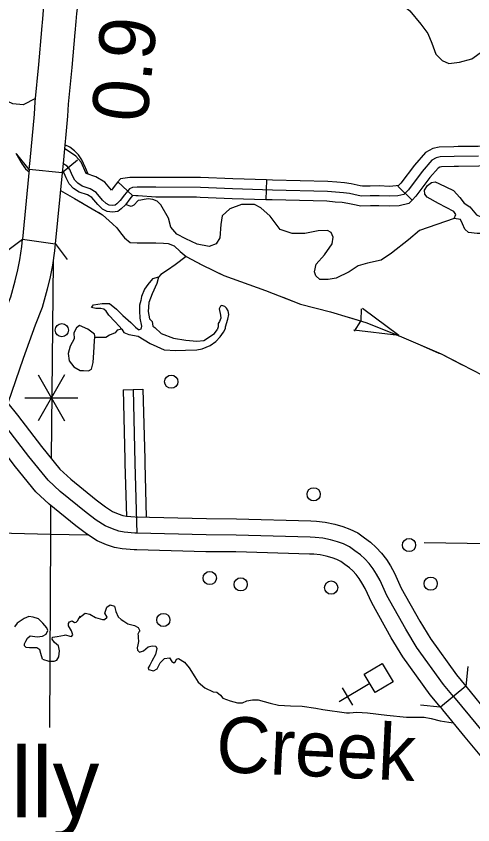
# Model space of a CAD drawing. Extents: x 1369979 to 1371646, y 379997 to 381064.
# Drawn here: x 1370730.7 to 1370771.1, y 380459 to 380530.6 of the extents above; entities that cross this region are included whole.
import ezdxf

# ---------------------------------------------------------------- set-up
doc = ezdxf.new("R2010")
doc.units = 0
doc.layers.add('R_Border Notes', color=7, linetype='Continuous')
doc.layers.add('R_Draft', color=7, linetype='Continuous')

msp = doc.modelspace()

# ---------------------------------------------------------------- linework, layer by layer
at = {"layer": 'R_Border Notes'}
for p, q in [((1370731.853, 380517.038), (1370731.853, 380517.038)), ((1370752.855, 380516.113), (1370752.803, 380514.356)), ((1370739.706, 380515.944), (1370740.998, 380514.746)), ((1370764.488, 380515.56), (1370765.732, 380514.318)), ((1370761.235, 380504.703), (1370761.199, 380503.633)), ((1370764.561, 380502.327), (1370761.337, 380504.732)), ((1370760.628, 380502.711), (1370761.195, 380503.62)), ((1370764.561, 380502.327), (1370760.567, 380502.798)), ((1370734.974, 380498.843), (1370732.63, 380494.784)), ((1370732.63, 380498.843), (1370734.974, 380494.784)), ((1370740.161, 380497.53), (1370741.918, 380497.572)), ((1370731.458, 380496.814), (1370736.146, 380496.814)), ((1370759.287, 380469.915), (1370761.993, 380471.537)), ((1370760.493, 380469.613), (1370759.589, 380471.121))]:
    msp.add_line(p, q, dxfattribs=at)
for points in [[(1370732.968, 380529.439), (1370733.061, 380530.397), (1370733.109, 380531.14), (1370733.214, 380531.981), (1370733.366, 380532.79), (1370733.562, 380533.756), (1370733.744, 380534.501), (1370733.962, 380535.343), (1370734.086, 380535.716)], [(1370736.87, 380534.806), (1370736.585, 380533.785), (1370736.421, 380533.117), (1370736.241, 380532.229), (1370736.11, 380531.53), (1370736.027, 380530.863), (1370735.981, 380530.161), (1370735.885, 380529.159)], [(1370756.709, 380532.362), (1370757.256, 380532.103), (1370757.558, 380532.031), (1370758.004, 380532.031), (1370758.436, 380532.103), (1370758.796, 380532.304), (1370759.17, 380532.722), (1370759.415, 380533.039), (1370759.818, 380533.328), (1370760.063, 380533.4), (1370760.869, 380533.385), (1370761.906, 380533.011), (1370763.403, 380532.593), (1370764.396, 380532.059), (1370765.548, 380531.094), (1370766.498, 380529.912)], [(1370766.498, 380529.912), (1370767.143, 380529.084), (1370767.489, 380528.219), (1370767.834, 380527.254), (1370768.395, 380526.706), (1370769, 380526.418), (1370769.936, 380526.534), (1370771.016, 380526.836), (1370771.966, 380527.528), (1370772.311, 380527.715), (1370772.743, 380527.787), (1370773.161, 380527.643), (1370773.852, 380527.297), (1370774.283, 380526.721), (1370774.586, 380525.842), (1370774.902, 380525.035), (1370774.974, 380524.631), (1370774.917, 380524.271), (1370775.046, 380524.041), (1370775.406, 380523.724), (1370775.838, 380523.551), (1370776.932, 380523.306)], [(1370731.853, 380517.038), (1370731.931, 380517.84), (1370732.321, 380521.954), (1370732.369, 380523.026), (1370732.701, 380526.34), (1370732.967, 380529.425)], [(1370735.886, 380529.173), (1370735.618, 380526.068), (1370735.292, 380522.815), (1370735.245, 380521.751), (1370734.848, 380517.559), (1370734.768, 380516.749)], [(1370732.399, 380523.334), (1370731.306, 380522.765), (1370730.388, 380522.853), (1370729.559, 380523.227), (1370728.257, 380524.353)], [(1370737.052, 380516.628), (1370736.836, 380517.197), (1370736.498, 380517.893), (1370736.21, 380518.333), (1370735.864, 380518.705), (1370735.45, 380519.031), (1370735.005, 380519.225)], [(1370769.829, 380519.066), (1370769.444, 380519.061), (1370768.127, 380519.033), (1370767.561, 380518.907), (1370766.927, 380518.548), (1370765.945, 380517.43), (1370764.748, 380515.82), (1370764.488, 380515.56)], [(1370775.967, 380519.371), (1370774.882, 380519.308), (1370771.589, 380519.087), (1370769.829, 380519.066)], [(1370730.649, 380518.485), (1370731.139, 380517.65), (1370731.528, 380517.102), (1370731.833, 380516.837)], [(1370731.853, 380517.038), (1370730.739, 380518.398)], [(1370736.877, 380516.688), (1370736.458, 380517.685), (1370735.968, 380518.224), (1370734.975, 380518.899)], [(1370771.624, 380518.209), (1370769.459, 380518.183), (1370768.233, 380518.156), (1370767.881, 380518.078), (1370767.489, 380517.856), (1370766.628, 380516.877), (1370765.415, 380515.244), (1370765.011, 380514.84), (1370764.463, 380514.709), (1370763.733, 380514.67), (1370762.82, 380514.709), (1370762.033, 380514.696), (1370761.268, 380514.683), (1370760.968, 380514.748), (1370760.194, 380514.905), (1370759.659, 380514.983), (1370758.238, 380515.101), (1370753.372, 380515.218), (1370749.837, 380515.323), (1370746.994, 380515.453), (1370743.068, 380515.466), (1370741.411, 380515.466), (1370740.981, 380515.453), (1370740.733, 380515.323), (1370740.563, 380515.14), (1370740.29, 380514.801), (1370739.911, 380514.304), (1370739.611, 380513.991), (1370739.468, 380513.886), (1370739.207, 380513.847), (1370738.933, 380513.886), (1370738.672, 380514.017), (1370738.346, 380514.33), (1370737.778, 380515.016)], [(1370731.178, 380517.594), (1370731.528, 380517.102), (1370731.833, 380516.837)], [(1370736.128, 380517.863), (1370734.768, 380516.749)], [(1370737.778, 380515.016), (1370737.253, 380515.322), (1370736.525, 380515.57), (1370736.147, 380515.818), (1370735.873, 380516.105), (1370735.664, 380516.549), (1370735.455, 380517.045), (1370735.194, 380517.333), (1370734.829, 380517.581)], [(1370776.069, 380517.616), (1370774.992, 380517.553), (1370771.659, 380517.33), (1370769.85, 380517.308)], [(1370731.853, 380517.038), (1370731.249, 380510.88)], [(1370734.768, 380516.749), (1370731.853, 380517.038)], [(1370735.296, 380515.954), (1370735.129, 380516.311), (1370734.954, 380516.726), (1370734.784, 380516.913)], [(1370769.85, 380517.308), (1370769.474, 380517.304), (1370768.339, 380517.28), (1370768.2, 380517.249), (1370768.052, 380517.165), (1370767.312, 380516.324), (1370766.083, 380514.669), (1370765.732, 380514.318)], [(1370767.782, 380515.962), (1370768.117, 380515.802), (1370769.39, 380515.18), (1370769.952, 380514.558), (1370770.337, 380514.054), (1370770.84, 380513.728), (1370771.432, 380513.017), (1370771.817, 380512.839), (1370773.297, 380513.313), (1370773.474, 380513.758), (1370773.652, 380514.439), (1370773.386, 380515.565), (1370772.646, 380516.75), (1370772.566, 380517.055)], [(1370734.768, 380516.749), (1370734.15, 380510.472)], [(1370739.706, 380515.944), (1370739.367, 380515.524), (1370739.133, 380515.217), (1370738.547, 380515.925), (1370737.741, 380516.393), (1370736.877, 380516.688)], [(1370746.648, 380516.333), (1370743.069, 380516.345), (1370741.398, 380516.345), (1370740.751, 380516.326), (1370739.915, 380516.202), (1370739.704, 380515.941)], [(1370752.855, 380516.113), (1370749.871, 380516.201), (1370747.016, 380516.332), (1370746.648, 380516.333)], [(1370759.084, 380515.913), (1370758.284, 380515.979), (1370753.396, 380516.097), (1370752.855, 380516.113)], [(1370740.998, 380514.746), (1370740.751, 380514.439), (1370740.357, 380513.923), (1370739.998, 380513.548), (1370739.697, 380513.328), (1370739.209, 380513.255), (1370738.756, 380513.32), (1370738.33, 380513.533), (1370737.916, 380513.931), (1370737.393, 380514.562), (1370737.009, 380514.786), (1370736.266, 380515.039), (1370735.769, 380515.365), (1370735.383, 380515.77), (1370735.296, 380515.954)], [(1370764.565, 380515.637), (1370764.337, 380515.583), (1370763.728, 380515.55), (1370762.831, 380515.588), (1370762.018, 380515.575), (1370761.355, 380515.564), (1370761.148, 380515.608), (1370760.345, 380515.771), (1370759.759, 380515.857), (1370759.084, 380515.913)], [(1370766.863, 380514.843), (1370766.85, 380515.197), (1370767.104, 380515.621), (1370767.459, 380515.892), (1370767.782, 380515.962)], [(1370734.614, 380515.178), (1370735.861, 380514.465), (1370737.416, 380513.572)], [(1370734.614, 380515.178), (1370735.861, 380514.465), (1370736.627, 380514.025)], [(1370746.642, 380514.576), (1370743.066, 380514.588), (1370741.484, 380514.695), (1370741.281, 380514.695), (1370740.995, 380514.748)], [(1370769.449, 380512.691), (1370769.597, 380513.047), (1370769.419, 380513.313), (1370768.087, 380514.024), (1370767.081, 380514.587), (1370766.863, 380514.843)], [(1370741.492, 380514.281), (1370741.103, 380513.876), (1370740.866, 380513.758), (1370740.367, 380513.936)], [(1370762.996, 380509.017), (1370761.788, 380508.751), (1370760.959, 380508.514), (1370760.16, 380507.98), (1370759.006, 380507.417), (1370758.295, 380507.299), (1370757.585, 380507.299), (1370757.23, 380507.625), (1370757.111, 380507.98), (1370757.259, 380508.662), (1370757.97, 380509.491), (1370758.651, 380510.469), (1370758.739, 380511.062), (1370758.562, 380511.447), (1370758.236, 380511.624), (1370757.437, 380511.595), (1370756.253, 380511.358), (1370755.128, 380511.358), (1370754.062, 380511.713), (1370753.174, 380512.898), (1370752.346, 380513.639), (1370751.783, 380513.935), (1370750.629, 380513.935), (1370749.593, 380513.55), (1370748.912, 380512.928), (1370748.823, 380512.158), (1370748.734, 380511.002), (1370748.409, 380510.469), (1370747.787, 380510.232), (1370746.721, 380510.439), (1370745.715, 380510.913), (1370744.916, 380511.328), (1370744.383, 380511.921), (1370744.176, 380512.721), (1370743.491, 380513.925), (1370743.169, 380514.248), (1370742.78, 380514.383), (1370742.373, 380514.434), (1370742.034, 380514.383), (1370741.73, 380514.332), (1370741.492, 380514.281)], [(1370752.803, 380514.356), (1370749.804, 380514.445), (1370746.972, 380514.575), (1370746.642, 380514.576)], [(1370758.939, 380514.161), (1370758.191, 380514.223), (1370753.349, 380514.34), (1370752.803, 380514.356)], [(1370765.732, 380514.318), (1370765.457, 380514.042), (1370764.59, 380513.836), (1370763.738, 380513.79), (1370762.808, 380513.83), (1370762.048, 380513.817), (1370761.18, 380513.802), (1370760.787, 380513.888), (1370760.043, 380514.039), (1370759.559, 380514.11), (1370758.939, 380514.161)], [(1370737.416, 380513.572), (1370738.347, 380513.032), (1370739.206, 380512.232), (1370739.591, 380511.876), (1370739.913, 380511.425), (1370740.288, 380510.992), (1370740.777, 380510.589), (1370741.391, 380510.56), (1370742.161, 380510.56), (1370743.054, 380510.543), (1370743.735, 380510.513), (1370744.149, 380510.484), (1370744.682, 380510.276), (1370745.215, 380509.773), (1370745.739, 380509.342), (1370747.192, 380508.558), (1370749.087, 380507.64), (1370752.757, 380506.336)], [(1370737.967, 380513.252), (1370738.347, 380513.032), (1370739.206, 380512.232), (1370739.591, 380511.876), (1370739.913, 380511.425), (1370740.288, 380510.992), (1370740.777, 380510.589), (1370741.391, 380510.56), (1370741.519, 380510.56)], [(1370770.011, 380512.602), (1370769.449, 380512.691), (1370766.4, 380511.624), (1370765.423, 380510.824), (1370763.913, 380509.639), (1370762.996, 380509.017)], [(1370773.735, 380511.98), (1370773.09, 380511.713), (1370772.409, 380511.358), (1370771.491, 380511.387), (1370770.722, 380511.476), (1370770.396, 380511.743), (1370770.189, 380512.217), (1370770.011, 380512.602)], [(1370721.739, 380488.601), (1370722.54, 380489.227), (1370723.088, 380489.761), (1370723.66, 380490.334), (1370724.101, 380490.939), (1370724.528, 380491.662), (1370725.153, 380492.669), (1370725.619, 380493.552), (1370726.92, 380496.593), (1370728.556, 380501.271), (1370729.633, 380504.281), (1370730.208, 380505.75), (1370730.596, 380507.186), (1370730.844, 380508.157), (1370731.004, 380509.044), (1370731.183, 380510.211), (1370731.249, 380510.88)], [(1370729.845, 380509.822), (1370731.249, 380510.88)], [(1370734.15, 380510.473), (1370734.091, 380509.846), (1370733.894, 380508.562), (1370733.708, 380507.533), (1370733.429, 380506.441), (1370732.995, 380504.831), (1370732.377, 380503.253), (1370731.318, 380500.294), (1370729.941, 380496.355)], [(1370731.249, 380510.88), (1370734.15, 380510.472)], [(1370734.15, 380510.473), (1370735.208, 380509.069)], [(1370743.066, 380510.543), (1370743.735, 380510.513), (1370744.149, 380510.484), (1370744.682, 380510.276), (1370745.215, 380509.773), (1370745.739, 380509.342), (1370747.123, 380508.595)], [(1370733.953, 380508.887), (1370733.783, 380491.463)], [(1370745.739, 380509.342), (1370744.775, 380508.607), (1370744.098, 380508.117), (1370743.508, 380507.728), (1370743.292, 380507.498)], [(1370743.292, 380507.498), (1370742.774, 380507.368), (1370742.356, 380506.849), (1370742.04, 380506.431), (1370741.795, 380505.783), (1370741.737, 380505.452), (1370741.608, 380505.019), (1370741.622, 380504.515), (1370741.651, 380503.867), (1370741.795, 380503.16), (1370741.723, 380502.901), (1370741.594, 380502.831)], [(1370743.292, 380507.498), (1370743.134, 380506.95), (1370742.731, 380506.028), (1370742.443, 380505.25), (1370742.371, 380504.472), (1370742.5, 380503.823), (1370742.601, 380503.694), (1370742.731, 380503.578), (1370742.803, 380503.175), (1370742.975, 380503.045), (1370743.537, 380502.526), (1370744.617, 380502.094), (1370745.711, 380501.921), (1370746.69, 380501.849), (1370747.309, 380501.892), (1370748.259, 380502.512), (1370748.475, 380502.843)], [(1370748.513, 380507.918), (1370749.087, 380507.64), (1370752.757, 380506.336), (1370752.858, 380506.296)], [(1370752.757, 380506.336), (1370755.865, 380505.121), (1370758.529, 380504.44), (1370761.637, 380503.492), (1370764.39, 380502.395), (1370768.297, 380500.707), (1370771.968, 380498.84), (1370775.055, 380497.405)], [(1370754.299, 380505.733), (1370755.865, 380505.121), (1370758.529, 380504.44), (1370758.729, 380504.379)], [(1370740.053, 380502.901), (1370739.795, 380503.16), (1370739.421, 380503.578), (1370738.903, 380504.126), (1370738.658, 380504.501), (1370738.442, 380504.673), (1370738.183, 380504.731), (1370737.737, 380504.731), (1370737.348, 380504.832), (1370737.535, 380505.063), (1370738.298, 380505.178), (1370738.946, 380505.178), (1370739.565, 380504.659), (1370740.126, 380504.097), (1370740.846, 380503.492), (1370741.249, 380503.088), (1370741.436, 380502.916), (1370741.594, 380502.831)], [(1370749.233, 380503.094), (1370749.441, 380503.795), (1370749.513, 380504.212), (1370749.469, 380504.515), (1370749.297, 380504.76), (1370749.153, 380504.918), (1370748.908, 380505.005), (1370748.778, 380504.947), (1370748.663, 380504.702), (1370748.778, 380504.14), (1370748.822, 380503.881), (1370748.692, 380503.593), (1370748.575, 380503.408)], [(1370760.209, 380503.927), (1370761.637, 380503.492), (1370764.39, 380502.395), (1370764.559, 380502.322)], [(1370740.053, 380502.901), (1370739.636, 380502.8), (1370739.448, 380502.584), (1370738.944, 380502.354), (1370738.628, 380502.166), (1370738.023, 380502.152), (1370737.678, 380502.166), (1370737.62, 380502.469), (1370737.044, 380502.887), (1370736.31, 380503.218), (1370736.037, 380503.016), (1370735.806, 380502.57), (1370735.821, 380502.037), (1370735.475, 380501.388), (1370735.302, 380500.74), (1370735.374, 380500.106), (1370735.806, 380499.558), (1370736.353, 380499.227), (1370736.641, 380499.241), (1370737.102, 380499.212), (1370737.375, 380499.356), (1370737.505, 380499.962), (1370737.577, 380500.826), (1370737.634, 380501.878), (1370737.663, 380502.181)], [(1370748.575, 380503.408), (1370748.561, 380503.117), (1370748.475, 380502.843)], [(1370740.053, 380502.901), (1370740.211, 380502.613), (1370740.658, 380502.426), (1370741.478, 380502.267), (1370742.544, 380501.619), (1370743.134, 380501.359), (1370743.796, 380501.057), (1370744.818, 380500.999), (1370745.667, 380501.042), (1370746.675, 380501.057), (1370747.165, 380501.158), (1370747.856, 380501.446), (1370748.374, 380501.82), (1370748.763, 380502.209), (1370749.051, 380502.627), (1370749.223, 380502.973), (1370749.233, 380503.094)], [(1370765.979, 380501.709), (1370768.109, 380500.788)], [(1370768.109, 380500.788), (1370768.297, 380500.707), (1370770.182, 380499.748)], [(1370740.161, 380497.53), (1370740.309, 380491.344)], [(1370741.04, 380497.551), (1370741.196, 380491.022), (1370741.367, 380484.811)], [(1370741.918, 380497.572), (1370742.067, 380491.386)], [(1370741.918, 380497.572), (1370742.067, 380491.386)], [(1370729.941, 380496.355), (1370730.814, 380495.289), (1370732.94, 380492.507), (1370734.567, 380490.493), (1370735.521, 380489.608), (1370737.768, 380487.788), (1370738.606, 380487.161), (1370739.233, 380486.747), (1370739.724, 380486.548), (1370740.127, 380486.407), (1370740.452, 380486.351), (1370741.212, 380486.28)], [(1370741.374, 380483.346), (1370741.138, 380483.345), (1370740.068, 380483.444), (1370739.389, 380483.561), (1370738.689, 380483.806), (1370737.862, 380484.141), (1370736.92, 380484.764), (1370735.968, 380485.476), (1370733.601, 380487.394), (1370732.42, 380488.488), (1370730.636, 380490.696), (1370728.679, 380493.257)], [(1370740.309, 380491.344), (1370740.318, 380490.999), (1370740.447, 380486.295)], [(1370742.067, 380491.386), (1370742.075, 380491.045), (1370742.206, 380486.255)], [(1370733.743, 380487.279), (1370733.718, 380484.752)], [(1370741.212, 380486.28), (1370747.525, 380486.119), (1370750.202, 380486.095), (1370756.789, 380485.914), (1370757.265, 380485.888), (1370758.049, 380485.815), (1370758.886, 380485.641), (1370759.598, 380485.416), (1370760.22, 380485.199), (1370760.93, 380484.849), (1370761.519, 380484.433), (1370762.066, 380484.023), (1370762.572, 380483.567), (1370763.028, 380483.062), (1370763.461, 380482.504), (1370763.812, 380481.939), (1370764.19, 380481.281), (1370764.783, 380479.969), (1370766.416, 380477.041), (1370767.39, 380475.448)], [(1370729.103, 380484.85), (1370733.718, 380484.752)], [(1370733.718, 380484.752), (1370733.631, 380467.635)], [(1370733.718, 380484.752), (1370737.044, 380484.673)], [(1370766.797, 380484.015), (1370795.4, 380483.569)], [(1370764.919, 380473.874), (1370763.886, 380475.563), (1370762.164, 380478.65), (1370761.579, 380479.945), (1370761.298, 380480.434), (1370761.053, 380480.828), (1370760.78, 380481.18), (1370760.498, 380481.492), (1370760.203, 380481.759), (1370759.796, 380482.063), (1370759.428, 380482.323), (1370759.086, 380482.492), (1370758.673, 380482.636), (1370758.144, 380482.803), (1370757.615, 380482.913), (1370757.049, 380482.965), (1370756.669, 380482.986), (1370750.149, 380483.166), (1370747.475, 380483.19), (1370741.329, 380483.347)], [(1370736.261, 380477.328), (1370736.805, 380477.757), (1370737.22, 380477.668), (1370737.708, 380477.372), (1370738.329, 380477.18), (1370738.521, 380477.194), (1370738.743, 380477.387), (1370738.551, 380477.742), (1370738.714, 380478.275), (1370739.024, 380478.483), (1370739.409, 380478.364), (1370739.527, 380477.905), (1370739.734, 380477.431), (1370739.986, 380477.18), (1370740.223, 380477.031), (1370740.563, 380476.809), (1370741.155, 380476.661), (1370741.495, 380476.469)], [(1370733.036, 380473.67), (1370732.87, 380474.188), (1370732.796, 380474.485), (1370732.515, 380474.662), (1370732.249, 380474.662), (1370731.879, 380474.677), (1370731.583, 380474.692), (1370731.435, 380474.855), (1370731.435, 380475.018), (1370731.539, 380475.269), (1370731.687, 380475.521), (1370731.923, 380475.743), (1370732.545, 380475.654), (1370733.033, 380475.699), (1370733.343, 380475.876), (1370733.491, 380476.202), (1370733.417, 380476.454), (1370733.062, 380476.869), (1370732.678, 380477.254), (1370732.19, 380477.387), (1370731.82, 380477.446), (1370731.391, 380477.283), (1370730.784, 380476.854), (1370730.547, 380476.543)], [(1370733.036, 380473.67), (1370733.598, 380473.492), (1370734.042, 380473.507), (1370734.293, 380473.596), (1370734.471, 380473.892), (1370734.515, 380474.425), (1370734.441, 380474.84), (1370734.086, 380475.151), (1370733.879, 380475.432), (1370733.923, 380475.61), (1370734.308, 380475.684), (1370734.959, 380475.788), (1370735.063, 380475.817), (1370735.432, 380475.699), (1370735.595, 380475.669), (1370735.699, 380475.832), (1370735.58, 380476.187), (1370735.329, 380476.632), (1370735.314, 380476.839), (1370735.403, 380476.972), (1370735.654, 380477.061), (1370735.861, 380476.913), (1370736.009, 380476.943), (1370736.113, 380477.061), (1370736.261, 380477.328), (1370736.394, 380477.476)], [(1370741.581, 380476.128), (1370741.462, 380475.891), (1370741.492, 380475.773), (1370741.477, 380475.58), (1370741.507, 380475.24), (1370741.462, 380474.944), (1370741.388, 380474.677), (1370741.418, 380474.455), (1370741.596, 380474.292), (1370741.965, 380474.396), (1370742.365, 380474.751), (1370742.735, 380474.84), (1370743.045, 380474.81), (1370743.134, 380474.603), (1370743.016, 380474.1), (1370742.69, 380473.507), (1370742.513, 380473.152), (1370742.38, 380472.9), (1370742.409, 380472.767), (1370742.853, 380472.634), (1370743.164, 380472.826), (1370743.445, 380473.359), (1370743.815, 380473.729), (1370744.258, 380473.789), (1370744.466, 380473.463), (1370744.658, 380473.359), (1370744.791, 380473.463), (1370744.895, 380473.67), (1370745.057, 380473.744), (1370745.605, 380473.404), (1370746.019, 380472.915), (1370746.507, 380472.115), (1370746.788, 380471.627), (1370747.38, 380471.138), (1370748.135, 380470.783), (1370748.46, 380470.753)], [(1370741.495, 380476.469), (1370741.596, 380476.247), (1370741.609, 380476.112)], [(1370767.33, 380475.538), (1370769.659, 380472.296), (1370770.492, 380471.289)], [(1370768.237, 380469.42), (1370767.338, 380470.504), (1370764.919, 380473.874)], [(1370770.663, 380473.031), (1370770.494, 380471.281)], [(1370770.492, 380471.289), (1370768.237, 380469.42)], [(1370770.492, 380471.289), (1370772.659, 380468.639), (1370774.424, 380466.511)], [(1370748.46, 380470.753), (1370748.782, 380470.491), (1370748.99, 380470.21), (1370749.626, 380469.987), (1370750.277, 380469.795), (1370750.721, 380469.795), (1370751.105, 380469.973), (1370751.623, 380470.076), (1370752.126, 380470.076), (1370753.162, 380469.765), (1370753.916, 380469.602), (1370754.981, 380469.543), (1370756.017, 380469.514), (1370757.23, 380469.321), (1370757.851, 380469.203), (1370759.922, 380468.906), (1370760.189, 380468.921), (1370760.854, 380468.966), (1370761.801, 380468.906)], [(1370768.233, 380469.418), (1370766.483, 380469.588)], [(1370761.801, 380468.906), (1370763.511, 380468.714), (1370765.242, 380468.536), (1370766.796, 380468.536), (1370767.417, 380468.403), (1370768.216, 380468.211), (1370769.372, 380468.032)], [(1370768.237, 380469.42), (1370768.434, 380469.181), (1370770.397, 380466.778), (1370772.171, 380464.638)]]:
    msp.add_lwpolyline(points, dxfattribs=at)
msp.add_lwpolyline([(1370764.051, 380471.661), (1370762.482, 380470.721), (1370761.507, 380472.348), (1370763.076, 380473.288)], close=True, dxfattribs=at)
for centre in [(1370734.733, 380502.807), (1370744.42, 380498.247), (1370757.026, 380488.273), (1370765.466, 380483.781), (1370747.825, 380480.858), (1370750.566, 380480.297), (1370758.573, 380480.013), (1370767.383, 380480.36), (1370743.721, 380477.143)]:
    msp.add_circle(centre, 0.586, dxfattribs=at)
at = {"layer": 'R_Draft'}
msp.add_line((1370769.392, 380470.377), (1370773.326, 380465.595), dxfattribs=at)
for points in [[(1370741.366, 380484.846), (1370741.203, 380484.846), (1370740.265, 380484.933), (1370739.767, 380485.018), (1370739.219, 380485.21), (1370738.564, 380485.475), (1370737.783, 380485.991), (1370736.89, 380486.659), (1370734.584, 380488.528), (1370733.519, 380489.515), (1370731.816, 380491.623), (1370729.871, 380494.168)], [(1370766.198, 380474.656), (1370765.182, 380476.32), (1370763.505, 380479.325), (1370762.916, 380480.629), (1370762.585, 380481.205), (1370762.286, 380481.686), (1370761.931, 380482.144), (1370761.56, 380482.555), (1370761.157, 380482.918), (1370760.678, 380483.277), (1370760.197, 380483.616), (1370759.667, 380483.878), (1370759.146, 380484.059), (1370758.524, 380484.256), (1370757.838, 380484.398), (1370757.16, 380484.462), (1370756.73, 380484.485), (1370750.176, 380484.666), (1370747.5, 380484.689), (1370741.367, 380484.846)], [(1370769.392, 380470.377), (1370768.526, 380471.421), (1370766.137, 380474.749)]]:
    msp.add_lwpolyline(points, dxfattribs=at)

# ---------------------------------------------------------------- texts
at = {"layer": 'R_Border Notes'}
for s, rotation, p in [('0.9', 84.29471, (1370742.258, 380521.103)), ('Creek', 357.32191, (1370748.302, 380463.702))]:
    msp.add_text(s, height=4.95, rotation=rotation, dxfattribs=at).set_placement(p)
msp.add_text('Holly', height=6.1875, dxfattribs=at).set_placement((1370719.665, 380459.669))

doc.saveas('drawing.dxf')
